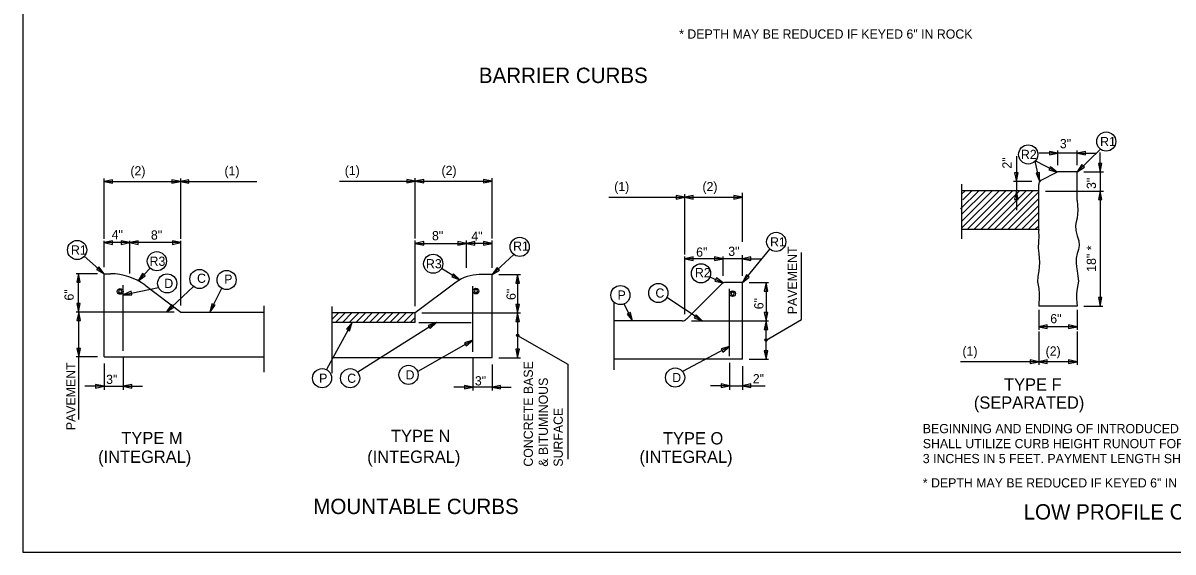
# Model space of a CAD drawing. Extents: x -439.1 to -407.9, y -458.1 to -436.2.
# Drawn here: x -439.11 to -420.39, y -458.05 to -449.44 of the extents above; entities that cross this region are included whole.
import ezdxf

# ---------------------------------------------------------------- set-up
doc = ezdxf.new("R2010")
doc.units = 0
for name, color, linetype in [('Draft_Named_Boundary', 7, 'Continuous'), ('Level 4', 7, 'Continuous'), ('Level 45', 7, 'Continuous')]:
    doc.layers.add(name, color=color, linetype=linetype)

msp = doc.modelspace()

# ---------------------------------------------------------------- linework, layer by layer
at = {"layer": 'Draft_Named_Boundary'}
msp.add_lwpolyline([(-439.109, -458.051), (-407.859, -458.051), (-407.859, -437.676), (-439.109, -437.676)], close=True, dxfattribs=at)
at = {"layer": 'Level 4'}
for p, q in [((-422.94, -451.607), (-422.94, -452.016)), ((-422.264, -451.556), (-422.577, -451.556)), ((-422.264, -451.751), (-422.264, -451.515)), ((-421.952, -451.556), (-422.264, -451.556)), ((-421.952, -451.751), (-421.952, -451.515)), ((-421.952, -451.556), (-421.639, -451.556)), ((-421.95, -451.86), (-421.573, -451.491)), ((-421.576, -451.86), (-421.576, -451.548)), ((-422.274, -451.866), (-422.632, -451.683)), ((-422.562, -452.014), (-422.632, -451.683)), ((-421.952, -451.86), (-422.246, -451.86)), ((-421.952, -452.328), (-421.952, -451.86)), ((-421.842, -451.86), (-421.521, -451.86)), ((-421.576, -451.853), (-421.576, -451.86)), ((-421.576, -451.86), (-421.576, -452.173)), ((-437.789, -452.953), (-437.789, -451.967)), ((-437.789, -452.018), (-435.305, -452.018)), ((-436.539, -452.953), (-436.539, -451.967)), ((-433.957, -452.012), (-431.474, -452.012)), ((-432.724, -452.947), (-432.724, -451.961)), ((-431.474, -452.947), (-431.474, -451.961)), ((-422.686, -452.016), (-422.986, -452.016)), ((-422.94, -452.016), (-422.94, -452.173)), ((-422.534, -451.995), (-422.281, -451.868)), ((-428.338, -453.209), (-428.338, -452.224)), ((-427.4, -453.002), (-427.4, -452.202)), ((-423.85, -452.463), (-423.559, -452.173)), ((-423.827, -452.772), (-423.228, -452.173)), ((-423.827, -452.551), (-423.449, -452.173)), ((-423.827, -452.219), (-423.78, -452.173)), ((-423.826, -452.951), (-423.826, -452.061)), ((-422.577, -452.172), (-423.826, -452.172)), ((-423.826, -452.661), (-423.338, -452.173)), ((-423.814, -452.317), (-423.67, -452.173)), ((-423.742, -452.798), (-423.117, -452.173)), ((-423.632, -452.798), (-423.007, -452.173)), ((-423.521, -452.798), (-422.896, -452.173)), ((-423.411, -452.798), (-422.786, -452.173)), ((-423.3, -452.798), (-422.675, -452.173)), ((-423.19, -452.798), (-422.577, -452.185)), ((-422.94, -452.173), (-422.94, -452.485)), ((-422.577, -452.797), (-422.577, -452.065)), ((-422.467, -452.173), (-421.524, -452.173)), ((-422.467, -452.173), (-421.53, -452.173)), ((-421.576, -452.173), (-421.576, -452.485)), ((-421.576, -452.173), (-421.576, -454.048)), ((-429.571, -452.274), (-427.4, -452.274)), ((-423.079, -452.798), (-422.577, -452.295)), ((-422.969, -452.798), (-422.577, -452.406)), ((-422.858, -452.798), (-422.577, -452.516)), ((-422.748, -452.798), (-422.577, -452.627)), ((-422.637, -452.798), (-422.577, -452.737)), ((-437.789, -453.41), (-437.789, -452.983)), ((-437.372, -453.515), (-437.372, -452.983)), ((-436.539, -454.035), (-436.539, -452.983)), ((-432.724, -454.049), (-432.724, -452.977)), ((-431.891, -453.424), (-431.891, -452.977)), ((-431.474, -453.424), (-431.474, -452.977)), ((-422.577, -452.797), (-423.826, -452.797)), ((-437.372, -453.012), (-437.789, -453.012)), ((-436.539, -453.012), (-437.372, -453.012)), ((-432.724, -453.025), (-431.891, -453.025)), ((-431.474, -453.025), (-431.891, -453.025)), ((-427.4, -453.662), (-426.954, -453.117)), ((-437.789, -453.52), (-438.111, -453.235)), ((-431.474, -453.533), (-431.119, -453.207)), ((-428.338, -454.178), (-428.338, -453.24)), ((-427.713, -453.275), (-428.338, -453.275)), ((-427.713, -453.275), (-428.025, -453.275)), ((-427.713, -453.553), (-427.713, -453.24)), ((-427.4, -453.275), (-427.713, -453.275)), ((-427.4, -453.553), (-427.4, -453.218)), ((-427.4, -453.275), (-427.088, -453.275)), ((-427.366, -453.275), (-427.4, -453.275)), ((-426.437, -454.267), (-426.437, -453.175)), ((-437.898, -453.52), (-438.244, -453.52)), ((-438.205, -454.145), (-438.205, -453.52)), ((-437.789, -454.874), (-437.789, -453.519)), ((-437.789, -453.519), (-437.685, -453.519)), ((-437.235, -453.634), (-437.04, -453.427)), ((-431.999, -453.619), (-432.295, -453.433)), ((-431.474, -453.533), (-431.683, -453.533)), ((-431.474, -454.888), (-431.474, -453.533)), ((-431.365, -453.533), (-431.009, -453.533)), ((-431.058, -453.533), (-431.058, -454.158)), ((-437.476, -454.776), (-437.476, -453.708)), ((-437.122, -453.707), (-436.539, -454.144)), ((-436.773, -454.138), (-436.333, -453.728)), ((-432.058, -453.658), (-432.724, -454.158)), ((-431.786, -454.789), (-431.786, -453.722)), ((-427.744, -453.693), (-428.308, -454.257)), ((-427.715, -453.672), (-427.925, -453.575)), ((-427.4, -453.662), (-427.67, -453.662)), ((-427.4, -454.912), (-427.4, -453.662)), ((-427.291, -453.662), (-426.976, -453.662)), ((-427.014, -453.662), (-427.014, -454.287)), ((-437.476, -453.862), (-436.904, -453.743)), ((-436.07, -454.145), (-435.875, -453.755)), ((-428.052, -454.287), (-428.629, -453.905)), ((-427.609, -454.86), (-427.609, -453.764)), ((-435.185, -455.125), (-435.185, -454.04)), ((-434.078, -455.138), (-434.078, -454.053)), ((-429.484, -455.084), (-429.484, -453.993)), ((-429.186, -454.287), (-429.325, -454.012)), ((-421.952, -454.047), (-422.577, -454.047)), ((-421.842, -454.048), (-421.535, -454.048)), ((-436.648, -454.145), (-438.244, -454.145)), ((-438.202, -454.874), (-438.202, -454.145)), ((-436.539, -454.144), (-435.185, -454.144)), ((-432.724, -454.158), (-434.078, -454.158)), ((-434.078, -454.261), (-433.975, -454.158)), ((-434.021, -454.315), (-433.865, -454.158)), ((-433.911, -454.315), (-433.754, -454.158)), ((-433.8, -454.315), (-433.644, -454.158)), ((-433.69, -454.315), (-433.534, -454.158)), ((-433.579, -454.315), (-433.423, -454.158)), ((-433.469, -454.315), (-433.313, -454.158)), ((-433.358, -454.315), (-433.202, -454.158)), ((-433.248, -454.315), (-433.092, -454.158)), ((-433.137, -454.315), (-432.981, -454.158)), ((-433.027, -454.315), (-432.871, -454.158)), ((-432.916, -454.315), (-432.76, -454.158)), ((-432.806, -454.315), (-432.724, -454.233)), ((-432.724, -454.314), (-432.724, -454.158)), ((-432.615, -454.158), (-431.009, -454.158)), ((-431.058, -454.158), (-431.058, -454.887)), ((-428.381, -454.287), (-429.484, -454.287)), ((-428.229, -454.287), (-426.976, -454.287)), ((-427.014, -454.6), (-426.437, -454.267)), ((-427.014, -454.912), (-427.014, -454.287)), ((-422.577, -454.109), (-422.577, -454.432)), ((-421.952, -454.109), (-421.952, -454.432)), ((-433.752, -454.315), (-434.168, -455.077)), ((-432.724, -454.314), (-434.078, -454.314)), ((-432.381, -454.315), (-433.66, -455.122)), ((-432.664, -454.314), (-431.814, -454.314)), ((-421.952, -454.382), (-422.577, -454.382)), ((-422.577, -454.462), (-422.577, -455.003)), ((-421.952, -454.462), (-421.952, -455.003)), ((-431.787, -454.601), (-432.683, -455.111)), ((-431.058, -454.523), (-430.243, -454.994)), ((-427.609, -454.706), (-428.375, -455.109)), ((-437.898, -454.874), (-438.244, -454.874)), ((-438.202, -455.894), (-438.202, -454.874)), ((-437.789, -454.874), (-435.185, -454.874)), ((-437.789, -454.983), (-437.789, -455.408)), ((-437.476, -454.886), (-437.476, -455.408)), ((-431.474, -454.888), (-434.078, -454.888)), ((-431.787, -454.899), (-431.787, -455.419)), ((-431.474, -454.997), (-431.474, -455.419)), ((-431.365, -454.887), (-431.009, -454.887)), ((-430.243, -454.994), (-430.243, -456.539)), ((-427.4, -454.912), (-429.484, -454.912)), ((-427.609, -454.97), (-427.609, -455.408)), ((-427.4, -455.022), (-427.4, -455.408)), ((-427.291, -454.912), (-426.976, -454.912)), ((-421.952, -454.953), (-423.847, -454.953)), ((-437.789, -455.353), (-438.101, -455.353)), ((-437.789, -455.353), (-437.476, -455.353)), ((-437.476, -455.353), (-437.164, -455.353)), ((-431.787, -455.366), (-432.099, -455.366)), ((-431.474, -455.366), (-431.787, -455.366)), ((-431.474, -455.366), (-431.162, -455.366)), ((-427.609, -455.344), (-427.921, -455.344)), ((-427.609, -455.344), (-427.4, -455.344)), ((-427.4, -455.344), (-427.088, -455.344)), ((-427.4, -455.344), (-427.028, -455.344))]:
    msp.add_line(p, q, dxfattribs=at)
for points in [[(-422.403, -451.585), (-422.264, -451.556), (-422.403, -451.528)], [(-421.814, -451.528), (-421.952, -451.556), (-421.814, -451.585)], [(-422.41, -451.828), (-422.274, -451.866), (-422.384, -451.777)], [(-422.41, -451.828), (-422.274, -451.866), (-422.384, -451.777)], [(-421.872, -451.743), (-421.95, -451.86), (-421.831, -451.784)], [(-421.872, -451.743), (-421.95, -451.86), (-421.831, -451.784)], [(-421.605, -451.722), (-421.576, -451.86), (-421.548, -451.722)], [(-437.65, -451.989), (-437.789, -452.018), (-437.65, -452.047)], [(-436.685, -452.047), (-436.547, -452.018), (-436.685, -451.989)], [(-436.409, -451.989), (-436.547, -452.018), (-436.409, -452.047)], [(-432.862, -452.041), (-432.724, -452.012), (-432.862, -451.983)], [(-432.586, -451.983), (-432.724, -452.012), (-432.586, -452.041)], [(-431.613, -452.041), (-431.474, -452.012), (-431.613, -451.983)], [(-422.968, -451.878), (-422.94, -452.016), (-422.911, -451.878)], [(-422.618, -451.884), (-422.562, -452.014), (-422.562, -451.872)], [(-422.618, -451.884), (-422.562, -452.014), (-422.562, -451.872)], [(-422.911, -452.311), (-422.94, -452.173), (-422.968, -452.311)], [(-421.548, -452.311), (-421.576, -452.173), (-421.605, -452.311)], [(-428.476, -452.303), (-428.338, -452.274), (-428.476, -452.246)], [(-428.2, -452.246), (-428.338, -452.274), (-428.2, -452.303)], [(-427.539, -452.303), (-427.4, -452.274), (-427.539, -452.246)], [(-437.65, -452.983), (-437.789, -453.012), (-437.65, -453.041)], [(-437.51, -453.041), (-437.372, -453.012), (-437.51, -452.983)], [(-437.234, -452.983), (-437.372, -453.012), (-437.234, -453.041)], [(-436.677, -453.041), (-436.539, -453.012), (-436.677, -452.983)], [(-432.586, -452.997), (-432.724, -453.025), (-432.586, -453.054)], [(-432.029, -453.054), (-431.891, -453.025), (-432.029, -452.997)], [(-431.753, -452.997), (-431.891, -453.025), (-431.753, -453.054)], [(-431.613, -453.054), (-431.474, -453.025), (-431.613, -452.997)], [(-428.2, -453.246), (-428.338, -453.275), (-428.2, -453.304)], [(-427.851, -453.304), (-427.713, -453.275), (-427.851, -453.246)], [(-427.262, -453.246), (-427.4, -453.275), (-427.262, -453.304)], [(-438.176, -453.658), (-438.205, -453.52), (-438.234, -453.658)], [(-437.911, -453.45), (-437.789, -453.52), (-437.873, -453.407)], [(-437.911, -453.45), (-437.789, -453.52), (-437.873, -453.407)], [(-437.162, -453.514), (-437.235, -453.634), (-437.12, -453.553)], [(-437.162, -453.514), (-437.235, -453.634), (-437.12, -453.553)], [(-432.131, -453.57), (-431.999, -453.619), (-432.101, -453.521)], [(-432.131, -453.57), (-431.999, -453.619), (-432.101, -453.521)], [(-431.392, -453.419), (-431.474, -453.533), (-431.353, -453.461)], [(-431.392, -453.419), (-431.474, -453.533), (-431.353, -453.461)], [(-431.03, -453.672), (-431.058, -453.533), (-431.087, -453.672)], [(-427.335, -453.537), (-427.4, -453.662), (-427.291, -453.574)], [(-427.335, -453.537), (-427.4, -453.662), (-427.291, -453.574)], [(-427.847, -453.638), (-427.71, -453.67), (-427.823, -453.586)], [(-427.847, -453.638), (-427.71, -453.67), (-427.823, -453.586)], [(-426.985, -453.801), (-427.014, -453.662), (-427.043, -453.801)], [(-437.347, -453.806), (-437.476, -453.862), (-437.335, -453.862)], [(-437.347, -453.806), (-437.476, -453.862), (-437.335, -453.862)], [(-421.605, -453.909), (-421.576, -454.048), (-421.548, -453.909)], [(-438.234, -454.006), (-438.205, -454.145), (-438.176, -454.006)], [(-436.691, -454.023), (-436.773, -454.138), (-436.652, -454.065)], [(-436.691, -454.023), (-436.773, -454.138), (-436.652, -454.065)], [(-436.034, -454.008), (-436.07, -454.145), (-435.983, -454.034)], [(-436.034, -454.008), (-436.07, -454.145), (-435.983, -454.034)], [(-431.087, -454.02), (-431.058, -454.158), (-431.03, -454.02)], [(-438.174, -454.283), (-438.202, -454.145), (-438.231, -454.283)], [(-431.03, -454.297), (-431.058, -454.158), (-431.087, -454.297)], [(-429.274, -454.177), (-429.186, -454.287), (-429.223, -454.151)], [(-429.274, -454.177), (-429.186, -454.287), (-429.223, -454.151)], [(-428.183, -454.235), (-428.052, -454.287), (-428.151, -454.187)], [(-428.183, -454.235), (-428.052, -454.287), (-428.151, -454.187)], [(-427.043, -454.149), (-427.014, -454.287), (-426.985, -454.149)], [(-426.985, -454.426), (-427.014, -454.287), (-427.043, -454.426)], [(-433.793, -454.45), (-433.752, -454.315), (-433.844, -454.422)], [(-433.793, -454.45), (-433.752, -454.315), (-433.844, -454.422)], [(-432.482, -454.413), (-432.381, -454.315), (-432.513, -454.364)], [(-432.482, -454.413), (-432.381, -454.315), (-432.513, -454.364)], [(-422.439, -454.354), (-422.577, -454.382), (-422.439, -454.411)], [(-422.09, -454.411), (-421.952, -454.382), (-422.09, -454.354)], [(-431.893, -454.694), (-431.787, -454.601), (-431.921, -454.644)], [(-431.893, -454.694), (-431.787, -454.601), (-431.921, -454.644)], [(-438.231, -454.736), (-438.202, -454.874), (-438.174, -454.736)], [(-431.087, -454.749), (-431.058, -454.887), (-431.03, -454.749)], [(-427.718, -454.795), (-427.609, -454.706), (-427.745, -454.745)], [(-427.718, -454.795), (-427.609, -454.706), (-427.745, -454.745)], [(-427.043, -454.774), (-427.014, -454.912), (-426.985, -454.774)], [(-422.715, -454.982), (-422.577, -454.953), (-422.715, -454.924)], [(-422.439, -454.924), (-422.577, -454.953), (-422.439, -454.982)], [(-422.09, -454.982), (-421.952, -454.953), (-422.09, -454.924)], [(-437.927, -455.381), (-437.789, -455.353), (-437.927, -455.324)], [(-437.338, -455.324), (-437.476, -455.353), (-437.338, -455.381)], [(-431.925, -455.395), (-431.787, -455.366), (-431.925, -455.337)], [(-431.336, -455.337), (-431.474, -455.366), (-431.336, -455.395)], [(-427.747, -455.372), (-427.609, -455.344), (-427.747, -455.315)], [(-427.262, -455.315), (-427.4, -455.344), (-427.262, -455.372)]]:
    msp.add_lwpolyline(points, close=True, dxfattribs=at)
for points in [[(-421.952, -452.329), (-421.944, -452.405), (-421.942, -452.482), (-421.943, -452.549), (-421.952, -452.615), (-421.966, -452.674), (-421.977, -452.733), (-421.973, -452.817), (-421.952, -452.902), (-421.926, -452.983), (-421.917, -453.062), (-421.931, -453.125), (-421.952, -453.188), (-421.965, -453.264), (-421.966, -453.342), (-421.961, -453.408), (-421.952, -453.475), (-421.937, -453.557), (-421.931, -453.639), (-421.94, -453.7), (-421.952, -453.761), (-421.959, -453.843), (-421.959, -453.925), (-421.957, -453.986), (-421.952, -454.048)], [(-422.577, -452.798), (-422.578, -452.829), (-422.578, -452.861), (-422.577, -452.881), (-422.577, -452.902), (-422.581, -453.002), (-422.584, -453.101), (-422.582, -453.145), (-422.577, -453.188), (-422.568, -453.263), (-422.564, -453.338), (-422.568, -453.407), (-422.577, -453.475), (-422.591, -453.563), (-422.595, -453.65), (-422.587, -453.706), (-422.577, -453.761), (-422.57, -453.848), (-422.571, -453.935), (-422.573, -453.991), (-422.577, -454.048)]]:
    msp.add_lwpolyline(points, dxfattribs=at)
for centre, radius in [((-421.477, -451.367), 0.156), ((-422.747, -451.577), 0.156), ((-438.228, -453.133), 0.156), ((-431.024, -453.082), 0.156), ((-426.849, -453.001), 0.156), ((-436.93, -453.316), 0.156), ((-432.432, -453.357), 0.156), ((-428.073, -453.513), 0.156), ((-436.762, -453.677), 0.156), ((-436.237, -453.605), 0.156), ((-435.795, -453.621), 0.156), ((-429.385, -453.867), 0.156), ((-428.768, -453.833), 0.156), ((-437.527, -453.808), 0.0468), ((-431.736, -453.802), 0.0468), ((-427.558, -453.844), 0.0468), ((-431.058, -454.523), 0.0208), ((-427.014, -454.6), 0.0208), ((-432.834, -455.166), 0.156), ((-434.241, -455.221), 0.156), ((-433.784, -455.221), 0.156), ((-428.494, -455.21), 0.156)]:
    msp.add_circle(centre, radius, dxfattribs=at)
for centre, radius, start, end in [((-422.246, -451.938), 0.0781, 90, 116.5651), ((-422.499, -452.065), 0.0781, 116.565, 180), ((-437.684, -454.457), 0.937, 53.1301, 90), ((-431.683, -454.158), 0.625, 90, 126.8699), ((-427.67, -453.766), 0.104, 90, 134.9999), ((-437.527, -453.808), 0.026, 0, 180), ((-437.527, -453.808), 0.026, 180, 0), ((-431.736, -453.802), 0.026, 0, 180), ((-431.736, -453.802), 0.026, 180, 0), ((-427.558, -453.844), 0.026, 0, 180), ((-427.558, -453.844), 0.026, 180, 0), ((-428.381, -454.183), 0.104, 270, 315)]:
    msp.add_arc(centre, radius, start, end, dxfattribs=at)

# ---------------------------------------------------------------- texts
for s, height, p in [('BARRIER CURBS', 0.25, (-431.689, -450.414)), ('R1', 0.15, (-421.577, -451.442)), ('R2', 0.15, (-422.866, -451.652)), ('R1', 0.15, (-426.949, -453.076)), ('R1', 0.15, (-438.328, -453.208)), ('R1', 0.15, (-431.131, -453.145)), ('R3', 0.15, (-437.049, -453.391)), ('R3', 0.15, (-432.55, -453.432)), ('C', 0.15, (-436.276, -453.668)), ('P', 0.15, (-435.834, -453.683)), ('R2', 0.15, (-428.172, -453.576)), ('D', 0.15, (-436.809, -453.752)), ('P', 0.15, (-429.432, -453.942)), ('C', 0.15, (-428.815, -453.908)), ('P', 0.15, (-434.289, -455.296)), ('C', 0.15, (-433.832, -455.296)), ('D', 0.15, (-432.882, -455.241)), ('D', 0.15, (-428.542, -455.285)), ('TYPE F', 0.2, (-423.14, -455.424)), ('(SEPARATED)', 0.2, (-423.632, -455.717)), ('TYPE M', 0.2, (-437.508, -456.294)), ('TYPE N', 0.2, (-433.119, -456.261)), ('TYPE O', 0.2, (-428.692, -456.299)), ('(INTEGRAL)', 0.2, (-437.886, -456.599)), ('(INTEGRAL)', 0.2, (-433.506, -456.599)), ('(INTEGRAL)', 0.2, (-429.075, -456.599)), ('MOUNTABLE CURBS', 0.25, (-434.384, -457.433)), ('LOW PROFILE CURB', 0.25, (-422.822, -457.522))]:
    msp.add_text(s, height=height, dxfattribs=at).set_placement(p)
for s, p in [('PAVEMENT', (-426.511, -454.179)), ('PAVEMENT', (-438.256, -456.067)), ('CONCRETE BASE', (-430.81, -456.661)), ('& BITUMINOUS', (-430.566, -456.661)), ('SURFACE', (-430.323, -456.661))]:
    msp.add_text(s, height=0.15, rotation=90, dxfattribs=at).set_placement(p)
at = {"layer": 'Level 45'}
for s, p in [('* DEPTH MAY BE REDUCED IF KEYED 6" IN ROCK', (-428.429, -449.691)), ('3"', (-422.232, -451.476)), ('(2)', (-437.361, -451.919)), ('(1)', (-435.83, -451.919)), ('(1)', (-433.872, -451.913)), ('(2)', (-432.297, -451.913)), ('(1)', (-429.486, -452.175)), ('(2)', (-428.05, -452.175)), ('4"', (-437.666, -452.958)), ('8"', (-437.027, -452.964)), ('8"', (-432.452, -452.975)), ('4"', (-431.811, -452.983)), ('6"', (-428.152, -453.242)), ('3"', (-427.63, -453.229)), ('6"', (-422.388, -454.326)), ('(1)', (-423.818, -454.854)), ('(2)', (-422.464, -454.854)), ('3"', (-437.756, -455.314)), ('3"', (-431.754, -455.338)), ('2"', (-427.23, -455.304)), ('BEGINNING AND ENDING OF INTRODUCED LOW PROFILE CURB', (-424.463, -456.116)), ('SHALL UTILIZE CURB HEIGHT RUNOUT FORM O INCHES TO ', (-424.463, -456.36)), ('3 INCHES IN 5 FEET. PAYMENT LENGTH SHALL INCLUDE TAPERS.', (-424.463, -456.604)), ('* DEPTH MAY BE REDUCED IF KEYED 6" IN ROCK.', (-424.463, -457))]:
    msp.add_text(s, height=0.15, dxfattribs=at).set_placement(p)
for s, p in [('2"', (-423.019, -451.807)), ('3"', (-421.645, -452.14)), ('18" *', (-421.645, -453.488)), ('6"', (-438.284, -453.956)), ('6"', (-431.089, -453.947)), ('6"', (-427.057, -454.098))]:
    msp.add_text(s, height=0.15, rotation=90, dxfattribs=at).set_placement(p)

doc.saveas('drawing.dxf')
